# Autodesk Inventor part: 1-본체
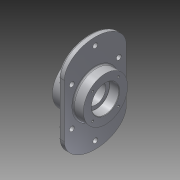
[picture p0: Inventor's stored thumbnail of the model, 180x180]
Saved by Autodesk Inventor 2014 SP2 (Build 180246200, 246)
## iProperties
Created: 2015-02
Part Number: 1-본체
Material: 알루미늄 6061
Document SubType Name: Modeling
Designer: 201-09
Density: 2.71 g/cm^3
Appearance: 알루미늄 - 평지
Mass: 1662.1 g
Surface Area: 942.609 cm^2
Volume: 613.321 cm^3
Author: 201-09
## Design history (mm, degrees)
sketch "스케치1"
  geometry: L1 (70, -60)-(70, 60); L2 (-70, 60)-(-70, -60); L3 (-70, -60)-(70, 60); L4 (70, -60)-(-70, 60); L5 (0, 110)-(0, 0); L6 (0, -110)-(0, 0); 2 further points; 2 other entities
  constraints: 12 end point, 2 midpoint, 2 point on line, 2 vertical, 1 parallel, 10 other
  dimensions: "d1" = 140 distance between parallel lines of L1 L2; "d5" = 50 distance of point (0, 60) L5.start; "d6" = 50 distance of point (0, -60) L6.start; "d7" = 120 distance of point (0, -60) point (0, 60); "d8" = 220 distance of L6.start L5.start; "d9" = 140 horizontal distance of L1.start L2.start; "d10" = 120 vertical distance of L2.end L1.end; "d11" = 110 distance of L5.start L5.end; "d12" = 120 vertical distance of L1.start L2.start
extrude "돌출1" new body sketch "스케치1" distance "d13" = 12; taper "d14" = 0 deg
fillet "모깎기1" dims "d15" = 3
node "작업 평면1"
sketch "스케치2"
  geometry: C1 r 50 at (0, 0); 1 further point
  constraints: 1 centre point, 1 coincident
  dimensions: "d17" = 100 diameter of C1
extrude "돌출2" join sketch "스케치2" distance "d18" = 70; taper "d19" = 0 deg
fillet "모깎기2" dims "d20" = 3
node "작업 평면2"
sketch "스케치3"
  geometry: L1 (-60, -70)-(60, -70) reference; L2 (60, 70)-(-60, 70) reference; L3 (60, -53)-(-60, -53); L4 (-60, 53)-(60, 53); L5 (93, 0)-(0, 0); L6 (43.5, 53)-(43.5, 0); C1 r 10 at (93, 0); C2 r 10 at (43.5, 53); C3 r 10 at (43.5, -53); 1 further point
  constraints: 8 end point, 4 parallel, 3 centre point, 3 vertical alignment, 2 coincident, 1 perpendicular, 1 point on line, 1 symmetric about line, 7 other
  dimensions: "d22" = 10 radius of C1; "d23" = 17 distance between parallel lines of L1 L3; "d24" = 93 distance of L5.start L5.end; "d25" = 53 distance between parallel lines of L3 L5; "d29" = 53 distance from line of L5 L6.start; "d30" = 43.5 distance from line of point (0, 0) L6; "d31" = 10 radius of C2
extrude "돌출3" join sketch "스케치3" stored distance "d26" = 70; taper "d27" = 0 deg
fillet "모깎기3" dims "d32" = 3
hole "구멍1" diameter "d35" = 62; stored, may be unused: countersink angle "d39" = 90 deg, drill point angle "d41" = 0 deg; dims "d33" = 10, "d34" = 10, "d36" = 6, "d37" = 4, "d38" = 2, "d40" = 22
hole "구멍2" diameter "d44" = 62; stored, may be unused: countersink angle "d48" = 90 deg, drill point angle "d50" = 0 deg; dims "d42" = 10, "d43" = 10, "d45" = 6, "d46" = 4, "d47" = 2, "d49" = 22
hole "구멍3" diameter "d53" = 45; stored, may be unused: countersink angle "d57" = 90 deg, drill point angle "d59" = 0 deg; dims "d51" = 10, "d52" = 10, "d54" = 6, "d55" = 4, "d56" = 2, "d58" = 22
sketch "스케치5"
  geometry: C1 r 10 at (-49.5, 53) reference; C2 r 10 at (0, 0) reference; C3 r 10 at (-136.5, 53) reference; C4 r 10 at (-186, 0) reference; C5 r 10 at (-136.5, -53) reference; C6 r 10 at (-49.5, -53) reference; 7 further points
  constraints: 6 coincident
hole "구멍4" sketch "스케치5" at (-49.5, 53), (-136.5, 53), (-186, 0), (-136.5, -53), (-49.5, -53), (0, 0) diameter "d60" = 11; stored, may be unused: countersink angle "d64" = 90 deg, drill point angle "d66" = 0 deg; dims "d61" = 6, "d62" = 4, "d63" = 2, "d65" = 22
chamfer "모따기1" distance "d67" = 1; stored, may be unused: second distance "d68" = 2, angle "d69" = 45 deg
fillet "모깎기4" dims "d70" = 0.3
sketch "스케치6"
  geometry: L1 (0, 0)-(-28.991, -28.991); L2 (0, 0)-(-41, 0); A1 r 41 centre (0, 0) between (-28.991, -28.991) and (-41, 0); 2 further points
  constraints: 4 end point, 2 coincident, 2 point on circle, 1 centre point, 1 horizontal
  dimensions: "d71" = 41 radius of A1; "d72" = 45 deg angle of L1 L2
hole "구멍5" sketch "스케치6" at (-28.991, -28.991) diameter "d73" = 4.917; stored, may be unused: countersink angle "d77" = 90 deg, drill point angle "d79" = 118 deg; dims "d74" = 10, "d75" = 4, "d76" = 2, "d78" = 13
sketch "스케치7"
  geometry: L1 (0, 0)-(-41, 0); L2 (0, 0)-(-28.991, -28.991); A1 r 41 centre (0, 0) between (-41, 0) and (-28.991, -28.991); 2 further points
  constraints: 4 end point, 2 coincident, 2 point on circle, 1 centre point, 1 horizontal
  dimensions: "d83" = 41 radius of A1; "d84" = 45 deg angle of L2 L1
hole "구멍6" sketch "스케치7" at (-28.991, -28.991) diameter "d85" = 4.917; stored, may be unused: countersink angle "d89" = 90 deg, drill point angle "d91" = 118 deg; dims "d86" = 10, "d87" = 4, "d88" = 2, "d90" = 13
sketch "스케치8"
  geometry: L1 (67.101, 14.518)-(67.101, -14.518); L2 (67.101, -14.518)-(62.899, -14.518); L3 (62.899, -14.518)-(62.899, 14.518); L4 (62.899, 14.518)-(67.101, 14.518); L5 (65, 14.518)-(65, -14.518); L6 (67.101, 0)-(62.899, 0); L7 (60, 70)-(-60, 70) reference; C1 r 5.5 at (93, 0) reference; 1 further point
  constraints: 4 end point, 4 midpoint, 2 other
  dimensions: "d95" = 29.03528 distance of L5.start L5.end; "d96" = 4.20285 distance of L6.start L6.end; "d97" = 65 distance from line of point (0, 0) L5; "d98" = 0 distance from line of C1.centre L6; "d99" = 90 deg angle of L7 L5
feature "엠보싱1" sketch "스케치8" dims "d1" = 140, "d100" = 1, "d101" = 0
node "솔리드1"
mirror "대칭1"
pattern_circular "원형 패턴1" dims angle "d81" = 360 deg
pattern_circular "원형 패턴2" dims angle "d93" = 360 deg
other parameters: "d16" = 23, "d21" = 5
